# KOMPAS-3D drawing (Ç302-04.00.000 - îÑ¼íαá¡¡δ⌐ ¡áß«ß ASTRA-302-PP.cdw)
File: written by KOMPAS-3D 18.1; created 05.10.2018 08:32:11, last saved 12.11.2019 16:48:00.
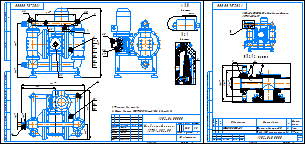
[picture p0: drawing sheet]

Sheet 1: A3, landscape
Sheet 2: A4, portrait

Document properties: Автор: Милов; Масса: 52.5; Форматы листов документа: A4, A3; Полное имя файла: ..\А302-01.00.000  - Мембранный насос ASTRA-302 ПВХ.a3d

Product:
- Part/product: (unnamed)
  - Component: Труба @2~50 полипроипилен  | pos. 0  | Раздел спецификации: Детали; Примечание: 87 мм
  - Component: Фланец с буртом -50  | designation МФ-01.00.000-01  | pos. 0  | Раздел спецификации: Детали; Примечание: Заим.

Title block, sheet 1: Наименование: Мембранный насос / ASTRA-302-PP; designation: А302-04.00.000; Масса: 52,5; scale: 1:5; sheet number: 1; Количество листов документа: 2; organisation: АО «Астерион»; Форматы листов документа: A3; stored path: \\192.168.87.28\Konstructor_doc\Мембранные насосы\Мембранный электропривод\А302-00.00.000 - ASTRA-302 (МЭ200)\3Д ПВХ\А302-01.00.000 - Мембранный насос ASTRA-302-PVC.cdw; Разработал: Лифлянд; Проверил: Борисенко; Т. контр.: Лучихин; Утвердил: Григорьева
Title block, sheet 2: sheet number: 2; Форматы листов документа: A4; stored path: D:\Мембранные насосы\Мембранный электропривод\А302-00.00.000 - ASTRA-302 (МЭ200)\А302-04.00.000 - Мембранный насос ASTRA-302-PP\А302-04.00.000 - Мембранный насос ASTRA-302-PP.cdw

Views: Проекционный вид 7, Местный разрез 1, Выносной элемент 8, Выносной элемент А, Выносной элемент, Выносной элемент Б, Вид:1
Referenced files in D:\Мембранные насосы\Мембранный электропривод\А302-00.00.000 - ASTRA-302 (МЭ200)\3Д ПВХ\: А302-01.31.000 - Корпус со встроенными стаканами.m3d, А302-01.30.001 - Прижим.m3d, А302-01.00.000  - Мембранный насос ASTRA-302 ПВХ.a3d, А302-01.15.000 - Мембрана.a3d, А302-01.10.000 - Рабочая камера.a3d, А302-01.10.000 - Рабочая камера.cdw, А302-01.05.000 - Корпус.a3d, А302-01.40.000 - Каркас.a3d, А302-01.40.000 - Каркас.cdw, Виброопора PCA-60 M10.m3d, А302-01.20.001 - Основание.m3d, А302-01.35.000 - Фланец.a3d, А302-04.35.003 - Опора подшиника.m3d, А302-04.35.004 - Стенка.m3d, А302-01.20.002 - Эксцентрик.m3d, FB 063 .m3d, А302-01.15.001 - Мембрана.m3d, А302-01.15.003 - Шайба.m3d, А302-01.15.008 - Кольцо плоское Ф4.m3d, А302-01.15.001-01- Мембрана.m3d, А302-01.15.007 - Заглушка.m3d, А302-01.15.002 - Упор.a3d, А302-01.12.000 - Крышка.a3d, А302-01.12.001 - Крышка.m3d, Втулка резьбовая М6 (шт.) Alutech.m3d, А302-01.11.000 - Крышка рабочей камеры.a3d, А302-01.10.001 - Седло.m3d, А302-01.10.002 3Д - Стакан.m3d, А302-01.30.000 - Прижим.a3d, А302-02.40.002 - Подставка 1.m3d, А302-02.40.003 - Подставка 2.m3d, А302-04.20.003 - Ползун из стержня.m3d, МФ-01.00.000-02 - Фланец с буртом -63.a3d, А302-01.15.002 - Упор.m3d, А302-01.15.009 - Кольцо плоское Ф4.m3d, А302-01.15.011 - Заглушка резьбовая.m3d
Referenced files in D:\1 ПКИ 3D\РТИ\Кольца ГОСТ 9833-76\: Кольцо 072-78-25 EPDM ГОСТ 9833-76.m3d
Referenced files in D:\1 ПКИ 3D\Полипропиленовые фитинги, трубы\Трубы\: Труба 50 PN10 S=4,6 FV PPR ф. FV PLAST.m3d
Referenced files in D:\1 ПКИ 3D\Полипропиленовые фитинги, трубы\: Тройник 50 FV PPR ф. FV PLAST.m3d, Труба ф50х4,6 FV PPR  (PN 10)  ф. FV PLAST.m3d, FV PPR Фальцевый бурт 50.m3d, FV PPR FE Свободный фланец к фальцевому бурту.m3d, Колено 90 ф50 ф.FV Plast.m3d, FV PPR Патрубок 50 арт. AA201050000.m3d
Referenced files in D:\3Д модели\Крепеж\: Гайка шестигранная самостопорящаяся с фланцем DIN 6927-M6 - A2-70.m3d
Referenced files in D:\Мембранные насосы\Мембранный электропривод\А302-00.00.000 - ASTRA-302 (МЭ200)\3Д ПВХ\Отработка\: Отвод ПВХ 90гр 50 арт.GIV050.m3d, Труба ПВХ PN10 50х2,4.m3d, Тройник равносторонний ПВХ 90гр 50 арт.TIV050.m3d, Штуцер для шланга 50х52х50 арт.AIV050052050.m3d, Квадратная внутренняя заглушка 140х140 мм.m3d, А302-01.20.000 - Мотор-редуктор.a3d, А302-01.05.002 - Ловитель.m3d, Труба профильная 25х25х1,5.m3d, Труба профильная 25х25х1,5-1.m3d
Referenced files in \\192.168.87.28\Konstructor_doc\Мембранные насосы\Мембранный электропривод\А302-00.00.000 - ASTRA-302 (МЭ200)\3Д ПВХ\: А302-01.15.000 - Мембрана.cdw, А302-01.10.000 - Рабочая камера.cdw, А302-01.05.000 - Корпус.cdw, А302-01.40.000 - Каркас.cdw
Referenced files in D:\Мембранные насосы\Мембранный электропривод\А302-00.00.000 - ASTRA-302 (МЭ200)\А302-04.00.000 - Мембранный насос ASTRA-302-PP\: А302-02.40.000 - Каркас.cdw, А302-02.10.000 - Рабочая камера.cdw, А302-02.15.000 - Мембрана.cdw
Referenced files in D:\1 ПКИ 3D\Двигатели\АИР\: Электродвигатель АИР 80А4 IM 3081 1,1кВт 1400 об..m3d
Referenced files in D:\1 ПКИ 3D\Редуктора NMRW\Редукторы\: Редуктор NMRW 063.m3d, Червячный мотор-редуктор NMRV063 АИР80.a3d
Referenced files in D:\Мембранные насосы\Мембранный электропривод\А302-00.00.000 - ASTRA-302 (МЭ200)\3Д\: А302-00.35.002 - Пластина.m3d, А302-00.35.001 - Труба 140х140х4.m3d, А302-00.20.004 - Вал.m3d, А302-00.20.003 - Ползун.m3d, А302-00.05.001 - Основание.m3d
Referenced files in C:\Program Files\ASCON\KOMPAS-3D v18\Libs\PartLib\DATA\VAULT\methods\kompas\3d\: PLib_Check_spring_rings_GOST_13942_911.m3d, PLib_Washer_1_712.m3d, PLib_Bolt_1_900.m3d, PLib_Washer_2_712.m3d, PLib_Nut_OST92_900.m3d, PLib_Screw_DIN_7984_1500.m3d, PLib_Key_prismatic_712.m3d, PLib_Screw_ISO_10642_1500.m3d, PLib_Bolt_1_ISO_1100.m3d, PLib_Nut_ISO_1100.m3d
Referenced files in D:\1 ПКИ 3D\1 Крепеж стандартный\Подшипник\: Подшипник 52х25х15 62052RSH SKF.m3d, Подшипник 80х40х18 6208-2RS1 SKF.m3d
Referenced files in D:\2 Стандартные изделия 3D\Гайки\DIN 6927\: Гайка шестигранная самостопорящаяся с фланцем DIN 6927-M5 - A2-70.m3d, Гайка шестигранная самостопорящаяся с фланцем DIN 6927-M6 - A2-70.m3d
Referenced files in D:\1 ПКИ 3D\ПВХ фитинги, трубы\: Труба PVC-U 50 3,7.m3d
Referenced files in D:\2 Стандартные изделия 3D\Винты\Din 912\: Винт DIN 912-М6х100-А2-70.m3d
Referenced files in D:\1 ПКИ 3D\2 Китай\: Шар PTFE ф60.m3d
Referenced files: Заготовка стакан.m3d
Referenced files in D:\1 ПКИ 3D\Крышечки NMRW (габаритные модели)\: МИКС К 00.00.001-04 - Крышка.m3d
Referenced files in C:\Program Files\ASCON\KOMPAS-3D v18\Libs\PARTLib\DATA\vault\Methods\Kompas\3D\: PLib_Screw_GOST_11738_1500.m3d
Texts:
  Шайба 6 30Х13 019 ГОСТ 6402-70
  Шайба
  ГОСТ
  Шайба C.6.21 ГОСТ 11371-78
  Гайка шестигранная самостопорящаяся
  с фланцем DIN 6927-M6-A2-70
  Гайка
  шестигранная
  самостопорящаяся
  фланцем
  DIN
  Отвод ПВХ 90   50 арт.GIV050
  Отвод ПВХ 90@1~ @2~50 арт.GIV050
  Винт с цилиндрической головкой
  и шестигранным углублением под ключ
  ГОСТ Р ИСО  4762-М8 x 40-6.8-A9J
  Винт
  цилиндрической
  головкой
  шестигранным
  углублением
  под
  ключ
  ИСО
  Нерж.
  ГОСТ Р ИСО  4762-М6 x 50-A2-70
  Винт с цилиндрической головкой и шестигранным углублением под ключ ГОСТ Р ИСО  4762-М6 x 50-A2-70
  Труба ПВХ PN10 50х2,4
  Шайба C.8.04.019 ГОСТ 11371-78
  Гайка М8-6H.5.019 ГОСТ 5915-70
  Шайба 8 30Х13 019 ГОСТ 6402-70
  Мембрана
  Рабочая камера
  Шайба C 12.21 ГОСТ 6958-78
  Корпус
  @100~)2xA3
  Тройник равносторонний
  ПВХ 90   50 арт.TIV050
  Тройник равносторонний / ПВХ 90@1~ @2~50 арт.TIV050
  Винт с потайной головкой и
  шестигранным углублением под ключ
  ГОСТ Р ИСО  10642-М8 x 40-8.8-A3J
  потайной
  Штуцер ПВХ для шланга 50х52х50
  арт.AIV050052050
  Штуцер ПВХ для шланга 50х52х50 / арт.AIV050052050
  Квадратная внутренняя заглушка 140х140 мм
  Каркас
  Виброопора PCA-60 M10
  МФ-01.00.000 - 01
  МФ-01.00.000 - 01
  Фланец с буртом -50
  Заим.
  Труба  50 полипроипилен
  Труба @2~50 полипроипилен
  Электродвигатель / АИР 80А4 IM 3081 1,1кВт 1400 об/мин
  Редуктор NMRW 063
  Мотор-редуктор / NMRV063 N P(кВт) V5 / P(мощн./дв.), i(передат. отн.) см. заказ
  Основание
  Пластина
  Труба 140х140х6
  Опора подшипника
  Стенка
  Фланец
  Эксцентрик
  Кольцо A25.65Г ГОСТ 13942-86
  Подшипник 52х25х15 62052RSH SKF
  Вал
  Ползун
  Болт М6-6gx40 ГОСТ 7805-70
  Гайка М6-6H.21.12Х18Н10Т ГОСТ 5915-70
  Шайба C.8.21 ГОСТ 11371-78
  Винт с цилиндрической головкой и шестигранным углублением под ключ ГОСТ Р ИСО 4762 - М8 x 25 - A2-70
  Гайка М8-6H.21.12Х18Н10Т ГОСТ 5915-70
  Шпонка 8x7x90 ГОСТ 23360-78
  FB 063
  Винт с цилиндрической головкой и шестигранным углублением под ключ ГОСТ Р ИСО 4762-М8 x 25-A2-70
  Подшипник 80х40х18 6208-2RS1 SKF
  Кольцо A40.65Г ГОСТ 13942-86
  Мотор-редуктор
  Ловитель
  Шайба C 8.04.019 ГОСТ 6958-78
  Болт М8-6gx35.58.019 ГОСТ 7805-70
  Винт с потайной головкой и шестигранным углублением под ключГОСТ Р ИСО 10642-М4x20-8.8-A3J
  Упор
  Болт с шестигранной головкой с фланцем ГОСТ Р 55739-М5 x 25-A2-70
  Гайка шестигранная с фланцем ГОСТ Р ИСО 4161 - M5 - A2-70
  Гайка шестигранная самостопорящаяся с фланцем / DIN 6927-M5-A2-70
  Кольцо плоское  / уплотнительное 5-13-10 Ф4
  Кольцо плоское Ф4
  Заглушка
  Заглушка резьбовая
  Болт с шестигранной головкой с фланцем ГОСТ Р 55739-М8 x 16-A2-70
  Крышка
  ART. 9058 ВТУЛКА РЕЗЬБОВАЯ С ВНЕШН. И ВНУТР. РЕЗЬБОЙ M6 / M10 X 14 ММ А1-НЕРЖ
  Труба полипропиленовая 50*4,6
  Отвод ПВХ 45@1~ @2~50 арт.HIV050
  Корпус со встроенными стаканами
  Шайба 6 30Х13 ГОСТ 6402-70
  Винт с цилиндрической головкой / и вн. шестигранником / DIN 912-М6х80-А2-70
  Крышка рабочей камеры
  Седло
  Шар @2~60mm PTFE / для мембранного насоса
  Стакан
  Прижим
  Труба 50 PN10 S=4,6 FV PPR ф. FV PLAST
  Гайка шестигранная самостопорящаяся с фланцем / DIN 6927-M6 - A2-70
  Винт с цилиндрической головкой и шестигранным углублением под ключ ГОСТ Р ИСО  4762-М6 x 40-A2-70
  Кольцо 072-078-25 / материал EPDM ГОСТ 9833-76
  Штифт 10х40
  Винт с цилиндрической головкой и шестигранным углублением под ключГОСТ Р ИСО 4762-М6x50-A2-70
  Гайка шестигранная самостопорящаяся / с фланцем DIN 6927-M6-A2-70
  Труба профильная 20х20х1,5 / Ст3 ГОСТ 380-2005
  Опора
  Подставка 1
  Подставка 2
  Винт с потайной головкой и шестигранным углублением под ключГОСТ Р ИСО 10642-М8x40-8.8-A3J
  Винт с цилиндрической головкой и шестигранным углублением под ключГОСТ Р ИСО 4762-М8x40-6.8-A9J
  Штуцер PP-H для шланга 50х90х50 / арт.Georg Fischer 727 960 410
  Колено 90 @2~50 ф.FV Plast
  Тройник @2~50 FV PPR ф. "FV PLAST"
  Труба 50 PN10 S=4,6 FV PPR ф. "FV PLAST"
  МИКС К 00.00.001-04
  Шайба C.8.37 ГОСТ 11371-78
  Винт М8-6gx20 ГОСТ 11738-84
  Ползун из стержня
  Труба ф50х4,6 FV PPR  (PN 10) / ф. FV PLAST
  Бурт-50
  МБ-00.00.001
  Фланец-50
  МФ-00.00.002
  МФ-01.00.000
  Заглушка пластиковая круглая 130 Артикул: ILT130
Dimensions and other numbers on the sheet: 3; 2; 1; 87; 150; 110; 50; 4; 10; 0; 13; 5; 16; 7; 6; 18; 14; 9; 11; 12; 17; 8; 19; 15; 20; 71; 87 мм; 1:5; 52,5; 01; 02

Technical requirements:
  *Размеры для справок.
  Общие допуски ГОСТ 30893.2-mK (H14, h14,  t2/2).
